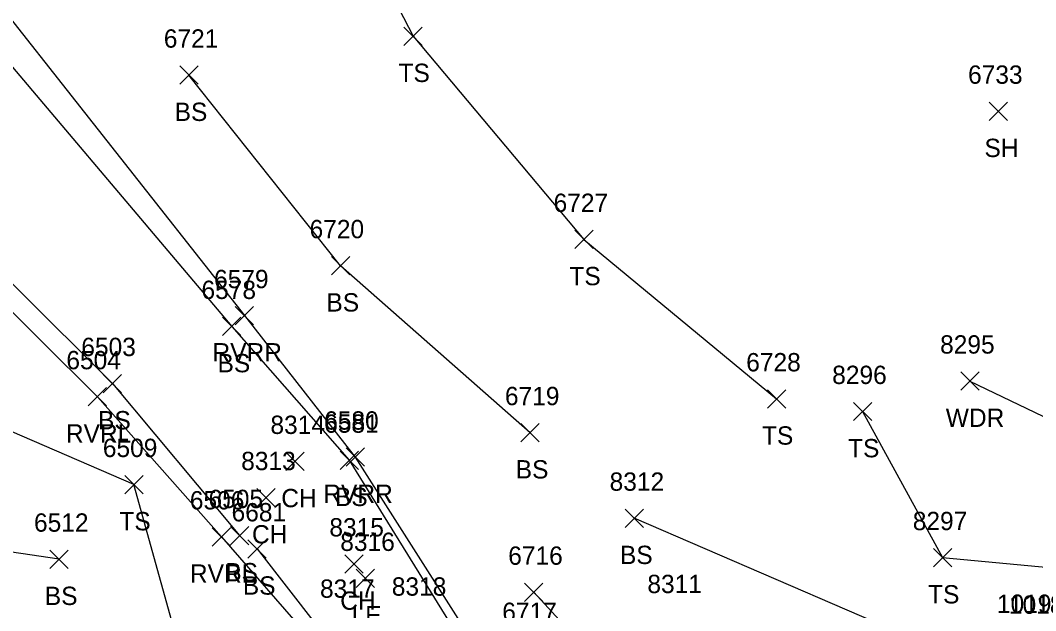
# Model space of a CAD drawing. Extents: x 1588028 to 1589597, y 137576 to 138176.
# Drawn here: x 1588875.5 to 1588986.3, y 137904.7 to 137969.2 of the extents above; entities that cross this region are included whole.
import ezdxf

# ---------------------------------------------------------------- set-up
doc = ezdxf.new("R2010")
doc.units = 0
for name, color, linetype in [('C_I', 7, 'Continuous'), ('L_A', 7, 'Continuous'), ('L_I', 7, 'Continuous'), ('L_TIC', 7, 'Continuous'), ('LAWA', 7, 'Continuous'), ('LAWE', 7, 'Continuous'), ('LELB', 7, 'Continuous')]:
    doc.layers.add(name, color=color, linetype=linetype)

msp = doc.modelspace()

# ---------------------------------------------------------------- linework, layer by layer
at = {"layer": 'L_TIC'}
for points in [[(1588917.38, 137966.44), (1588919.38, 137968.44)], [(1588919.38, 137966.44), (1588917.38, 137968.44)], [(1588892.93, 137962.19), (1588894.93, 137964.19)], [(1588894.93, 137962.19), (1588892.93, 137964.19)], [(1588981.22, 137958.25), (1588983.22, 137960.25)], [(1588983.22, 137958.25), (1588981.22, 137960.25)], [(1588936.02, 137944.26), (1588938.02, 137946.26)], [(1588938.02, 137944.26), (1588936.02, 137946.26)], [(1588909.48, 137941.39), (1588911.48, 137943.39)], [(1588911.48, 137941.39), (1588909.48, 137943.39)], [(1588898.99, 137935.94), (1588900.99, 137937.94)], [(1588900.99, 137935.94), (1588898.99, 137937.94)], [(1588897.61, 137934.76), (1588899.61, 137936.76)], [(1588899.61, 137934.76), (1588897.61, 137936.76)], [(1588884.58, 137928.53), (1588886.58, 137930.53)], [(1588886.58, 137928.53), (1588884.58, 137930.53)], [(1588978.13, 137928.8), (1588980.13, 137930.8)], [(1588980.13, 137928.8), (1588978.13, 137930.8)], [(1588882.95, 137927.09), (1588884.95, 137929.09)], [(1588884.95, 137927.09), (1588882.95, 137929.09)], [(1588957.03, 137926.86), (1588959.03, 137928.86)], [(1588959.03, 137926.86), (1588957.03, 137928.86)], [(1588966.42, 137925.48), (1588968.42, 137927.48)], [(1588968.42, 137925.48), (1588966.42, 137927.48)], [(1588930.14, 137923.17), (1588932.14, 137925.17)], [(1588932.14, 137923.17), (1588930.14, 137925.17)], [(1588911.08, 137920.5), (1588913.08, 137922.5)], [(1588913.08, 137920.5), (1588911.08, 137922.5)], [(1588904.51, 137920.03), (1588906.51, 137922.03)], [(1588906.51, 137920.03), (1588904.51, 137922.03)], [(1588910.42, 137920.16), (1588912.42, 137922.16)], [(1588912.42, 137920.16), (1588910.42, 137922.16)], [(1588886.93, 137917.51), (1588888.93, 137919.51)], [(1588888.93, 137917.51), (1588886.93, 137919.51)], [(1588901.32, 137916.08), (1588903.32, 137918.08)], [(1588903.32, 137916.08), (1588901.32, 137918.08)], [(1588941.51, 137913.83), (1588943.51, 137915.83)], [(1588943.51, 137913.83), (1588941.51, 137915.83)], [(1588896.47, 137911.79), (1588898.47, 137913.79)], [(1588898.47, 137911.79), (1588896.47, 137913.79)], [(1588898.45, 137911.94), (1588900.45, 137913.94)], [(1588900.45, 137911.94), (1588898.45, 137913.94)], [(1588900.37, 137910.49), (1588902.37, 137912.49)], [(1588902.37, 137910.49), (1588900.37, 137912.49)], [(1588975.15, 137909.53), (1588977.15, 137911.53)], [(1588977.15, 137909.53), (1588975.15, 137911.53)], [(1588878.77, 137909.36), (1588880.77, 137911.36)], [(1588880.77, 137909.36), (1588878.77, 137911.36)], [(1588910.94, 137908.84), (1588912.94, 137910.84)], [(1588912.94, 137908.84), (1588910.94, 137910.84)], [(1588912.19, 137907.26), (1588914.19, 137909.26)], [(1588914.19, 137907.26), (1588912.19, 137909.26)], [(1588930.55, 137905.75), (1588932.55, 137907.75)], [(1588932.55, 137905.75), (1588930.55, 137907.75)]]:
    msp.add_lwpolyline(points, dxfattribs=at)
at = {"layer": 'LAWA'}
msp.add_lwpolyline([(1588979.13, 137929.8), (1588992.38, 137923.42), (1589010.56, 137910.15), (1589033.48, 137893.69), (1589028.71, 137887.38), (1589019.12, 137885.67), (1588981.21, 137898.09), (1588946.07, 137903.66)], dxfattribs=at)
at = {"layer": 'LAWE'}
for points in [[(1588434.56, 138062.89), (1588458.47, 138076.79), (1588495.54, 138110.89), (1588517.72, 138151.17), (1588540.38, 138168.38), (1588562.32, 138170.6), (1588586.16, 138148.71), (1588635.49, 138130.01), (1588676.05, 138127.99), (1588706.09, 138118.66), (1588727.82, 138096.85), (1588770.39, 138065.1), (1588798.8, 138043.18), (1588827.56, 138018.04), (1588869.93, 137975.12), (1588899.99, 137936.94), (1588912.08, 137921.5), (1588926.82, 137898.29), (1588932.86, 137884.09), (1588938.83, 137878.76)], [(1588441.02, 138044.54), (1588465.05, 138060.11), (1588492.43, 138083.39), (1588521.86, 138113.88), (1588530.72, 138143.54), (1588545.57, 138151.23), (1588554.85, 138142.99), (1588577.1, 138115.96), (1588614.25, 138110.98), (1588643.88, 138111.05), (1588664.41, 138106.89), (1588688.53, 138102.18), (1588718.75, 138082.48), (1588743.28, 138056.23), (1588764.53, 138038.44), (1588797.04, 138013.98), (1588814.47, 138001.04), (1588852.47, 137959.37), (1588883.95, 137928.09), (1588897.47, 137912.79), (1588913.44, 137894.45), (1588920.69, 137884.16), (1588921.99, 137878.45)]]:
    msp.add_lwpolyline(points, dxfattribs=at)
at = {"layer": 'LELB'}
for points in [[(1588682.05, 138125.09), (1588705.48, 138117.82), (1588727.76, 138095.08), (1588769.43, 138063.36), (1588798.46, 138041.61), (1588826.19, 138016.5), (1588867.28, 137972.84), (1588898.61, 137935.76), (1588911.42, 137921.16), (1588925.66, 137898.09), (1588931.8, 137883.5), (1588937.54, 137876.95)], [(1588667.09, 138110.74), (1588688.84, 138110.6), (1588719.17, 138088.33), (1588744.4, 138063.38), (1588766.27, 138045.61), (1588798.27, 138018.43), (1588815.99, 138001.93), (1588854.1, 137960.89), (1588885.58, 137929.53), (1588899.45, 137912.94)], [(1588882.47, 138025.87), (1588903.77, 137995.7), (1588918.38, 137967.44), (1588937.02, 137945.26), (1588958.03, 137927.86)], [(1588879.77, 137910.36), (1588853.42, 137914.24), (1588857.54, 137933.72), (1588843.04, 137939.37), (1588832.61, 137973.66), (1588809.98, 137996.61)], [(1588931.14, 137924.17), (1588910.48, 137942.39), (1588893.93, 137963.19)], [(1588898.43, 137890.84), (1588893.87, 137897.04), (1588887.93, 137918.51), (1588870.83, 137925.89), (1588860.16, 137926.88)], [(1588967.42, 137926.48), (1588976.15, 137910.53), (1588993.6, 137908.9), (1589008.07, 137903.02), (1589028.71, 137887.38)], [(1588981.21, 137898.09), (1588942.51, 137914.83)], [(1588901.37, 137911.49), (1588914.27, 137894.87), (1588922.25, 137884.64), (1588924.34, 137877.72)], [(1588945.89, 137891.11), (1588931.55, 137906.75)]]:
    msp.add_lwpolyline(points, dxfattribs=at)

# ---------------------------------------------------------------- texts
at = {"layer": 'C_I'}
msp.add_text('1018', height=2, dxfattribs=at).set_placement((1588983.38, 137904.4))
at = {"layer": 'L_A'}
for s, p in [('TS', (1588916.79, 137962.44)), ('BS', (1588892.37, 137958.19)), ('SH', (1588980.71, 137954.25)), ('TS', (1588935.43, 137940.26)), ('BS', (1588908.93, 137937.39)), ('RVRR', (1588896.5, 137931.94)), ('BS', (1588897.05, 137930.76)), ('BS', (1588884.02, 137924.53)), ('WDR', (1588976.49, 137924.8)), ('RVRL', (1588880.51, 137923.09)), ('TS', (1588956.44, 137922.86)), ('TS', (1588965.83, 137921.48)), ('BS', (1588929.58, 137919.17)), ('CH', (1588904, 137916.03)), ('RVRR', (1588908.59, 137916.5)), ('BS', (1588909.86, 137916.16)), ('TS', (1588886.34, 137913.51)), ('CH', (1588900.81, 137912.08)), ('BS', (1588940.95, 137909.83)), ('RVRL', (1588894.04, 137907.79)), ('BS', (1588897.89, 137907.94)), ('BS', (1588899.81, 137906.49)), ('BS', (1588878.21, 137905.36)), ('TS', (1588974.56, 137905.53)), ('CH', (1588910.43, 137904.84)), ('LE', (1588911.67, 137903.26))]:
    msp.add_text(s, height=2, dxfattribs=at).set_placement(p)
at = {"layer": 'L_I'}
for s, p in [('6721', (1588891.19, 137966.19)), ('6733', (1588978.92, 137962.25)), ('6727', (1588933.71, 137948.26)), ('6720', (1588907.09, 137945.39)), ('6579', (1588896.67, 137939.94)), ('6578', (1588895.3, 137938.76)), ('8295', (1588975.87, 137932.8)), ('6503', (1588882.19, 137932.53)), ('6504', (1588880.56, 137931.09)), ('6728', (1588954.72, 137930.86)), ('8296', (1588964.1, 137929.48)), ('6719', (1588928.4, 137927.17)), ('8314', (1588902.82, 137924.03)), ('6581', (1588908.68, 137924.16)), ('6580', (1588908.68, 137924.5)), ('6509', (1588884.54, 137921.51)), ('8313', (1588899.63, 137920.08)), ('8312', (1588939.82, 137917.83)), ('6506', (1588894.03, 137915.79)), ('6505', (1588896.07, 137915.94)), ('6681', (1588898.58, 137914.49)), ('6512', (1588877.03, 137913.36)), ('8315', (1588909.25, 137912.84)), ('8297', (1588972.89, 137913.53)), ('8316', (1588910.44, 137911.26)), ('6716', (1588928.76, 137909.75)), ('8317', (1588908.23, 137906.15)), ('8318', (1588916.06, 137906.38)), ('8311', (1588943.94, 137906.66)), ('1019', (1588982.07, 137904.5)), ('6717', (1588928.11, 137903.62))]:
    msp.add_text(s, height=2, dxfattribs=at).set_placement(p)

doc.saveas('drawing.dxf')
